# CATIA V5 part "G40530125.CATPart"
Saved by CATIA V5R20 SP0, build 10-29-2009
Part number: G40530125
Revision: 4
Definition: design
Nomenclature: G40530125
Source: made
Description: NOT SPECIFIED
Bounding box of the stored display mesh (mm): x -62.5 to 62.5, y -12.5 to 12.5, z -25 to 0
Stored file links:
  C:\Users\Raffaele\Desktop\3D X SITO CF\BOLEX\29-GUIDE STRIP REF 405\G40530125.CATPart
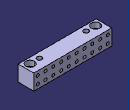
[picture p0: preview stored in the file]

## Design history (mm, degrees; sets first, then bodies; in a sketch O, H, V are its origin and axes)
Body1 "MANIFOLD_SOLID_BREP #3622" (main body)
  Solid1: solid without history
Body2 "MANIFOLD_SOLID_BREP #3760"
  Solid2: solid without history
Body3 "MANIFOLD_SOLID_BREP #3872"
  Solid3: solid without history
Body4 "MANIFOLD_SOLID_BREP #3984"
  Solid4: solid without history
Body5 "MANIFOLD_SOLID_BREP #4096"
  Solid5: solid without history
Body6 "MANIFOLD_SOLID_BREP #4208"
  Solid6: solid without history
Body7 "MANIFOLD_SOLID_BREP #4320"
  Solid7: solid without history
Body8 "MANIFOLD_SOLID_BREP #4432"
  Solid8: solid without history
Body9 "MANIFOLD_SOLID_BREP #4544"
  Solid9: solid without history
Body10 "MANIFOLD_SOLID_BREP #4656"
  Solid10: solid without history
Body11 "MANIFOLD_SOLID_BREP #4768"
  Solid11: solid without history
Body12 "MANIFOLD_SOLID_BREP #4880"
  Solid12: solid without history
Body13 "MANIFOLD_SOLID_BREP #4992"
  Solid13: solid without history
Body14 "MANIFOLD_SOLID_BREP #5104"
  Solid14: solid without history
Body15 "MANIFOLD_SOLID_BREP #5216"
  Solid15: solid without history
Body16 "MANIFOLD_SOLID_BREP #5328"
  Solid16: solid without history
Body17 "MANIFOLD_SOLID_BREP #5440"
  Solid17: solid without history
Body18 "MANIFOLD_SOLID_BREP #5552"
  Solid18: solid without history
Body19 "MANIFOLD_SOLID_BREP #5664"
  Solid19: solid without history
Body20 "MANIFOLD_SOLID_BREP #5776"
  Solid20: solid without history
Body21 "MANIFOLD_SOLID_BREP #5914"
  Solid21: solid without history
Body22 "MANIFOLD_SOLID_BREP #6052"
  Solid22: solid without history
Body23 "MANIFOLD_SOLID_BREP #6190"
  Solid23: solid without history
Body24 "MANIFOLD_SOLID_BREP #6328"
  Solid24: solid without history
Body25 "MANIFOLD_SOLID_BREP #6466"
  Solid25: solid without history
Body26 "MANIFOLD_SOLID_BREP #6604"
  Solid26: solid without history
Body27 "MANIFOLD_SOLID_BREP #6742"
  Solid27: solid without history
Body28 "MANIFOLD_SOLID_BREP #6880"
  Solid28: solid without history
Body29 "MANIFOLD_SOLID_BREP #6992"
  Solid29: solid without history
Body30 "MANIFOLD_SOLID_BREP #7104"
  Solid30: solid without history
